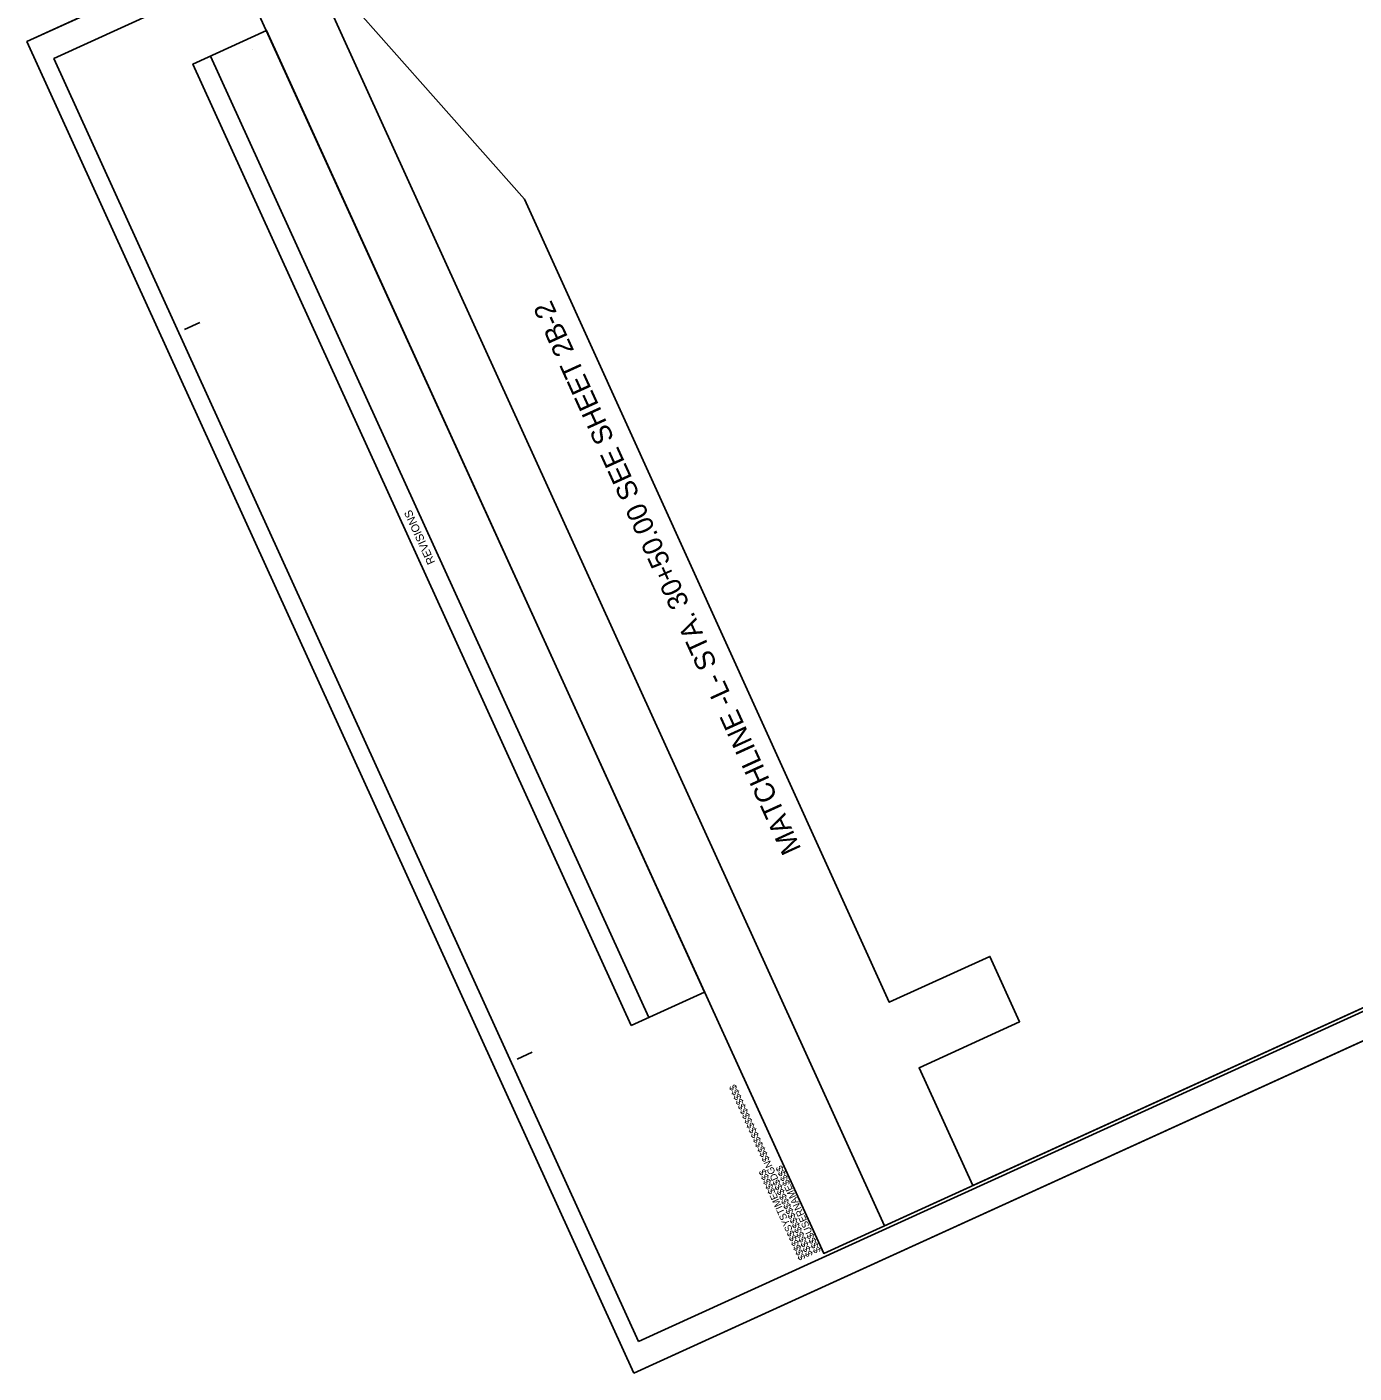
# Model space of a CAD drawing. Extents: x 2249053 to 2251039, y 663030 to 664800.
# Drawn here: x 2249053 to 2250046, y 663030 to 664038 of the extents above; entities that cross this region are included whole.
import ezdxf

# ---------------------------------------------------------------- set-up
doc = ezdxf.new("R2010")
doc.units = 0
for name, color, linetype in [('Matchline', 7, 'Continuous'), ('Matchline Text', 7, 'Continuous'), ('Sheet Block Revision CELL', 7, 'Continuous'), ('Sheet Clip Boundary CELL', 7, 'Continuous'), ('Sheet Cutting Line CELL', 7, 'Continuous'), ('Sheet Layout Plan Border', 7, 'Continuous'), ('Sheet North Arrow Point CELL', 7, 'Continuous'), ('Sheet Plan CELL', 7, 'Continuous'), ('Sheet Plan Layout CELL', 7, 'Continuous'), ('Sheet Plot Border Inside CELL', 7, 'Continuous'), ('Sheet Plot Border Outside CELL', 7, 'Continuous')]:
    doc.layers.add(name, color=color, linetype=linetype)

msp = doc.modelspace()

# ---------------------------------------------------------------- linework, layer by layer
at = {"layer": 'Matchline'}
msp.add_line((2249673.4, 663362.4), (2249425.3, 663908.7), dxfattribs=at)
at = {"layer": 'Sheet Block Revision CELL'}
msp.add_line((2249518.3, 663296.5), (2249190.4, 664015.9), dxfattribs=at)
msp.add_lwpolyline([(2249505.1, 663290.4), (2249177.2, 664009.9), (2249232.3, 664035), (2249560.1, 663315.5)], close=True, dxfattribs=at)
at = {"layer": 'Sheet Clip Boundary CELL'}
msp.add_lwpolyline([(2249425.3, 663908.7), (2249673.4, 663362.4), (2249698.3, 663307.8), (2249773.6, 663342.1), (2249795.8, 663293.3), (2249720.6, 663258.8), (2249760.8, 663170.7), (2250968.8, 663721.1), (2250621.1, 664484.2), (2250480.7, 664420.2), (2250393, 664612.7), (2249259.4, 664096.1)], close=True, dxfattribs=at)
at = {"layer": 'Sheet Cutting Line CELL'}
for p, q in [((2250585, 664724.9), (2249053.1, 664026.8)), ((2249053.1, 664026.8), (2249507.1, 663030.3)), ((2249507.1, 663030.3), (2251039.1, 663728.4))]:
    msp.add_line(p, q, dxfattribs=at)
at = {"layer": 'Sheet Layout Plan Border'}
msp.add_lwpolyline([(2249694.8, 663140.6), (2250968.8, 663721.1), (2250621.1, 664484.2), (2250448.8, 664405.7), (2250361.1, 664598.1), (2249259.4, 664096.1)], close=True, dxfattribs=at)
at = {"layer": 'Sheet North Arrow Point CELL'}
msp.add_line((2249221.6, 664020.8), (2249221.6, 664020.8), dxfattribs=at)
at = {"layer": 'Sheet Plan CELL'}
for p, q in [((2249171, 663811.3), (2249182.4, 663816.5)), ((2249419.8, 663265.3), (2249431.2, 663270.5)), ((2249649.3, 663119.9), (2249649.3, 663119.9))]:
    msp.add_line(p, q, dxfattribs=at)
for points in [[(2250578.9, 664697.4), (2249213.9, 664075.3), (2249649.3, 663119.9), (2251014.2, 663741.9)], [(2249649.3, 663119.9), (2249213.9, 664075.3), (2250396.8, 664614.4), (2250459, 664477.9), (2250641.1, 664560.8), (2251014.2, 663741.9)]]:
    msp.add_lwpolyline(points, close=True, dxfattribs=at)
at = {"layer": 'Sheet Plan Layout CELL'}
msp.add_lwpolyline([(2249213.9, 664075.3), (2249649.3, 663119.9), (2251014.2, 663741.9), (2250666.5, 664504.9), (2250448.8, 664405.7), (2250361.1, 664598.1)], close=True, dxfattribs=at)
at = {"layer": 'Sheet Plot Border Inside CELL'}
msp.add_lwpolyline([(2249510.6, 663053.9), (2251026.6, 663744.8), (2250589.2, 664704.8), (2249073.2, 664014)], close=True, dxfattribs=at)
at = {"layer": 'Sheet Plot Border Outside CELL'}
msp.add_lwpolyline([(2249507.1, 663030.3), (2251039.1, 663728.4), (2250585, 664724.9), (2249053.1, 664026.8)], close=True, dxfattribs=at)

# ---------------------------------------------------------------- texts
at = {"layer": 'Matchline Text'}
msp.add_text('MATCHLINE -L- STA. 30+50.00 SEE SHEET 2B-2', height=15, rotation=114.4979, dxfattribs=at).set_placement((2249632.6, 663422.6))
at = {"layer": 'Sheet Block Revision CELL'}
msp.add_text('REVISIONS', height=6, rotation=114.4979, dxfattribs=at).set_placement((2249358.6, 663637.1))
at = {"layer": 'Sheet Plan CELL'}
for s, p in [('$$$$$$$$$$$$$$$$DGN$$$$$$$$$$$$$$$$', (2249641.3, 663118.9)), ('$$$$$$SYSTIME$$$$$', (2249635.8, 663116.3)), ('$$$$USERNAME$$$$', (2249647.3, 663121.6))]:
    msp.add_text(s, height=5.25, rotation=114.4979, dxfattribs=at).set_placement(p)

doc.saveas('drawing.dxf')
